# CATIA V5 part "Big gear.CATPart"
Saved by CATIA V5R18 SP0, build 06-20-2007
Part number: Part2
Bounding box of the stored display mesh (mm): x -27.5 to 27.5, y -27.5 to 27.5, z 0 to 10
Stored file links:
  D:\shriniwas\v5_r19\c16_CAT_v5r19\c16_Part\Gear Joint\Big gear.CATPart
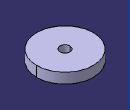
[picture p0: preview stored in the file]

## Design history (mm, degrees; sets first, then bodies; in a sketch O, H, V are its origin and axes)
Body1 (main body)
  Sketch1 on xy-plane, origin (0, 0, 0), H (1, 0, 0), V (0, 1, 0)
    circle A1 centre (0, 0) radius 27.5
    circle A2 centre (0, 0) radius 5
    radius A1 = 27.5
    radius A2 = 5
  Pad1: profile Sketch1, direction (0, 0, 1), length 10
